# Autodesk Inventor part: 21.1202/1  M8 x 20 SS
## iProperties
Created: 2006-02
Part Number: 21.1202/1  M8 x 20 SS
Material: Stainless Steel
Description: Cylinder Head Cap Screw
Document SubType Name: Modeling
Standard: DIN 7984
Designer: Andy Moles
Standards Organization: DIN
Language: en-US
Size Designation: M8 x 20
Categories: <MemberInstance><Categories><Category DisplayName="Fasteners" InternalName="e4da775c-781d-43d5-af7c-5136215cf5a6" Mnemonic="FSTN"><Category DisplayName="Bolts"
Mass: 12.6063 g
Surface Area: 10.1767 cm^2
Volume: 1.56018 cm^3
Density: 8.08 g/cm^3
Author: Andy Moles
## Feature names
1. Body [Revolution]
2. Slot [Extrusion]
3. Fillet1
4. Chamfer1
